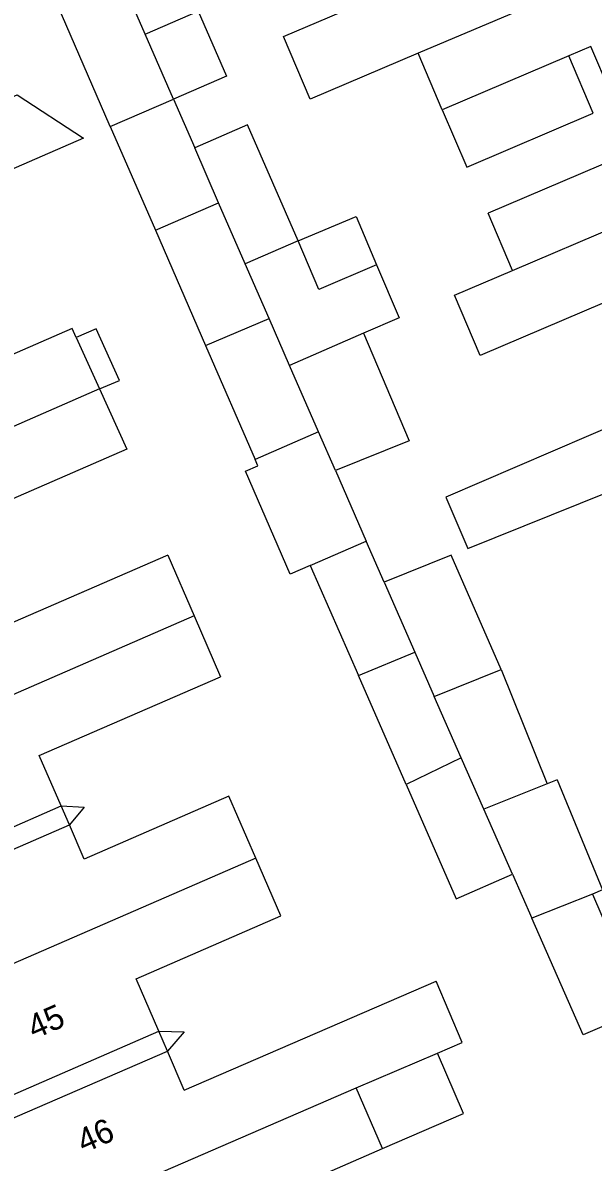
# Model space of a CAD drawing. Extents: x 132998 to 136004, y 396998 to 398512.
# Drawn here: x 133235.3 to 133258.98, y 397132.9 to 397180.2 of the extents above; entities that cross this region are included whole.
import ezdxf

# ---------------------------------------------------------------- set-up
doc = ezdxf.new("R2010")
doc.units = 0
for name, color, linetype in [('gg-afsc-erfafscheiding', 7, 'Continuous'), ('gg-anno-huisnummerreeks BGT', 7, 'Continuous'), ('gg-bbg-gedigitaliseerde bebouwing', 7, 'Continuous'), ('gg-bbg-gedigitaliseerde bebouwing onder overbouw', 7, 'Continuous'), ('gg-bbg-gedigitaliseerde bijgebouw', 7, 'Continuous'), ('gg-bbg-gedigitaliseerde overbouw', 7, 'Continuous'), ('gg-bbg-luifel en loopbrug', 7, 'Continuous'), ('gg-bbg-tussenscheiding', 7, 'Continuous')]:
    doc.layers.add(name, color=color, linetype=linetype)

msp = doc.modelspace()

# ---------------------------------------------------------------- linework, layer by layer
at = {"layer": 'gg-afsc-erfafscheiding'}
for points in [[(133236.894, 397147.687), (133237.85, 397147.637), (133237.237, 397146.898)], [(133240.949, 397138.334), (133241.996, 397138.313), (133241.305, 397137.513)]]:
    msp.add_lwpolyline(points, dxfattribs=at)
at = {"layer": 'gg-bbg-gedigitaliseerde bebouwing'}
for p, q in [((133252.72, 397176.59), (133251.72, 397178.936)), ((133257.97, 397178.829), (133252.72, 397176.59)), ((133260.725, 397174.898), (133254.623, 397172.295)), ((133255.635, 397169.923), (133254.623, 397172.295)), ((133253.224, 397168.894), (133255.635, 397169.923)), ((133237.519, 397167.139), (133238.49, 397164.998)), ((133238.49, 397164.998), (133239.626, 397162.493)), ((133239.626, 397162.493), (133231.838, 397159.108)), ((133241.317, 397158.098), (133233.716, 397154.791)), ((133241.317, 397158.098), (133242.413, 397155.576)), ((133242.413, 397155.576), (133243.512, 397153.05)), ((133242.008, 397135.893), (133252.461, 397140.414)), ((133242.008, 397135.893), (133241.305, 397137.513)), ((133249.143, 397135.983), (133252.513, 397137.419)), ((133250.237, 397133.46), (133249.143, 397135.983)), ((133244.264, 397130.876), (133250.237, 397133.46))]:
    msp.add_line(p, q, dxfattribs=at)
for points in [[(133251.72, 397178.936), (133247.231, 397177.035), (133246.124, 397179.629), (133256.756, 397184.156), (133256.091, 397185.716)], [(133259.7, 397177.302), (133258.882, 397179.218), (133257.97, 397178.829)], [(133262.824, 397170.034), (133254.29, 397166.393), (133253.224, 397168.894)], [(133237.519, 397167.139), (133237.354, 397167.503), (133229.628, 397164.144)], [(133264.714, 397165.605), (133252.863, 397160.502), (133253.786, 397158.379), (133259.587, 397160.713)], [(133236.894, 397147.687), (133235.985, 397149.776), (133243.512, 397153.05)], [(133244.974, 397145.526), (133243.856, 397148.096), (133237.852, 397145.484), (133237.237, 397146.898)], [(133240.949, 397138.334), (133240.005, 397140.505), (133246.02, 397143.121), (133244.974, 397145.526)], [(133252.513, 397137.419), (133253.549, 397137.861), (133252.461, 397140.414)]]:
    msp.add_lwpolyline(points, dxfattribs=at)
at = {"layer": 'gg-bbg-gedigitaliseerde bebouwing onder overbouw'}
for p, q in [((133229.447, 397144.45), (133236.894, 397147.687)), ((133229.79, 397143.661), (133237.237, 397146.898)), ((133233.511, 397135.101), (133240.949, 397138.334)), ((133233.868, 397134.28), (133241.305, 397137.513))]:
    msp.add_line(p, q, dxfattribs=at)
at = {"layer": 'gg-bbg-gedigitaliseerde bijgebouw'}
for p, q in [((133240.376, 397179.733), (133239.856, 397180.926)), ((133238.933, 397175.892), (133236.903, 397180.561)), ((133241.555, 397177.032), (133242.439, 397175.006)), ((133238.933, 397175.892), (133240.805, 397171.586)), ((133240.805, 397171.586), (133242.883, 397166.808)), ((133242.883, 397166.808), (133244.945, 397162.065)), ((133248.28, 397161.62), (133249.56, 397158.686)), ((133250.31, 397156.98), (133249.56, 397158.686)), ((133247.231, 397157.672), (133249.243, 397153.098)), ((133255.169, 397153.355), (133257.078, 397148.61)), ((133251.225, 397148.574), (133249.243, 397153.098)), ((133257.487, 397148.775), (133257.078, 397148.61)), ((133255.631, 397144.849), (133256.435, 397143.022))]:
    msp.add_line(p, q, dxfattribs=at)
for points in [[(133240.376, 397179.733), (133242.588, 397180.679), (133243.756, 397177.986), (133241.555, 397177.032)], [(133246.732, 397171.153), (133244.633, 397175.963), (133242.439, 397175.006)], [(133249.99, 397170.156), (133247.593, 397169.134), (133246.732, 397171.153)], [(133249.99, 397170.156), (133250.932, 397167.948), (133249.447, 397167.315)], [(133249.447, 397167.315), (133251.35, 397162.849), (133248.28, 397161.62)], [(133247.231, 397157.672), (133246.409, 397157.315), (133244.551, 397161.59), (133245.056, 397161.81), (133244.945, 397162.065)], [(133255.169, 397153.355), (133253.084, 397158.096), (133250.31, 397156.98)], [(133251.225, 397148.574), (133253.3, 397143.836), (133255.631, 397144.849)], [(133257.487, 397148.775), (133259.374, 397144.204), (133258.954, 397144.028)], [(133258.954, 397144.028), (133261.011, 397139.235), (133258.561, 397138.19), (133256.435, 397143.022)]]:
    msp.add_lwpolyline(points, dxfattribs=at)
at = {"layer": 'gg-bbg-gedigitaliseerde overbouw'}
for p, q in [((133237.237, 397146.898), (133236.894, 397147.687)), ((133241.305, 397137.513), (133240.949, 397138.334))]:
    msp.add_line(p, q, dxfattribs=at)
at = {"layer": 'gg-bbg-luifel en loopbrug'}
for points in [[(133252.72, 397176.59), (133253.733, 397174.213), (133258.983, 397176.451), (133257.97, 397178.829)], [(133232.753, 397176.204), (133235.068, 397177.211), (133237.816, 397175.407), (133233.831, 397173.675)], [(133246.732, 397171.153), (133249.137, 397172.156), (133249.99, 397170.156)], [(133238.49, 397164.998), (133239.314, 397165.356), (133238.343, 397167.497), (133237.519, 397167.139)], [(133250.237, 397133.46), (133253.599, 397134.915), (133252.513, 397137.419)]]:
    msp.add_lwpolyline(points, dxfattribs=at)
at = {"layer": 'gg-bbg-tussenscheiding'}
for p, q in [((133265.142, 397184.619), (133251.72, 397178.936)), ((133241.555, 397177.032), (133240.376, 397179.733)), ((133238.933, 397175.892), (133241.555, 397177.032)), ((133255.635, 397169.923), (133268.982, 397175.614)), ((133243.433, 397172.728), (133242.439, 397175.006)), ((133240.805, 397171.586), (133243.433, 397172.728)), ((133244.538, 397170.195), (133243.433, 397172.728)), ((133246.732, 397171.153), (133244.538, 397170.195)), ((133245.532, 397167.917), (133244.538, 397170.195)), ((133242.883, 397166.808), (133245.532, 397167.917)), ((133246.38, 397165.975), (133245.532, 397167.917)), ((133249.447, 397167.315), (133246.38, 397165.975)), ((133247.585, 397163.212), (133246.38, 397165.975)), ((133238.49, 397164.998), (133223.372, 397158.426)), ((133247.585, 397163.212), (133244.945, 397162.065)), ((133248.28, 397161.62), (133247.585, 397163.212)), ((133247.231, 397157.672), (133249.56, 397158.686)), ((133250.31, 397156.98), (133251.576, 397154.068)), ((133242.413, 397155.576), (133227.442, 397149.062)), ((133249.243, 397153.098), (133251.576, 397154.068)), ((133251.576, 397154.068), (133252.383, 397152.232)), ((133252.383, 397152.232), (133255.169, 397153.355)), ((133253.504, 397149.685), (133252.383, 397152.232)), ((133253.504, 397149.685), (133251.225, 397148.574)), ((133254.443, 397147.55), (133253.504, 397149.685)), ((133257.078, 397148.61), (133254.443, 397147.55)), ((133255.631, 397144.849), (133254.443, 397147.55)), ((133244.974, 397145.526), (133231.522, 397139.678)), ((133258.954, 397144.028), (133256.435, 397143.022)), ((133235.663, 397130.152), (133249.143, 397135.983))]:
    msp.add_line(p, q, dxfattribs=at)

# ---------------------------------------------------------------- texts
at = {"layer": 'gg-anno-huisnummerreeks BGT'}
for s, p in [('45', (133235.771, 397137.987)), ('46', (133237.826, 397133.258))]:
    msp.add_text(s, height=1, rotation=23.5, dxfattribs=at).set_placement(p)

doc.saveas('drawing.dxf')
